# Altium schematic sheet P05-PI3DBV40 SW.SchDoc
size 386 x 246 mm
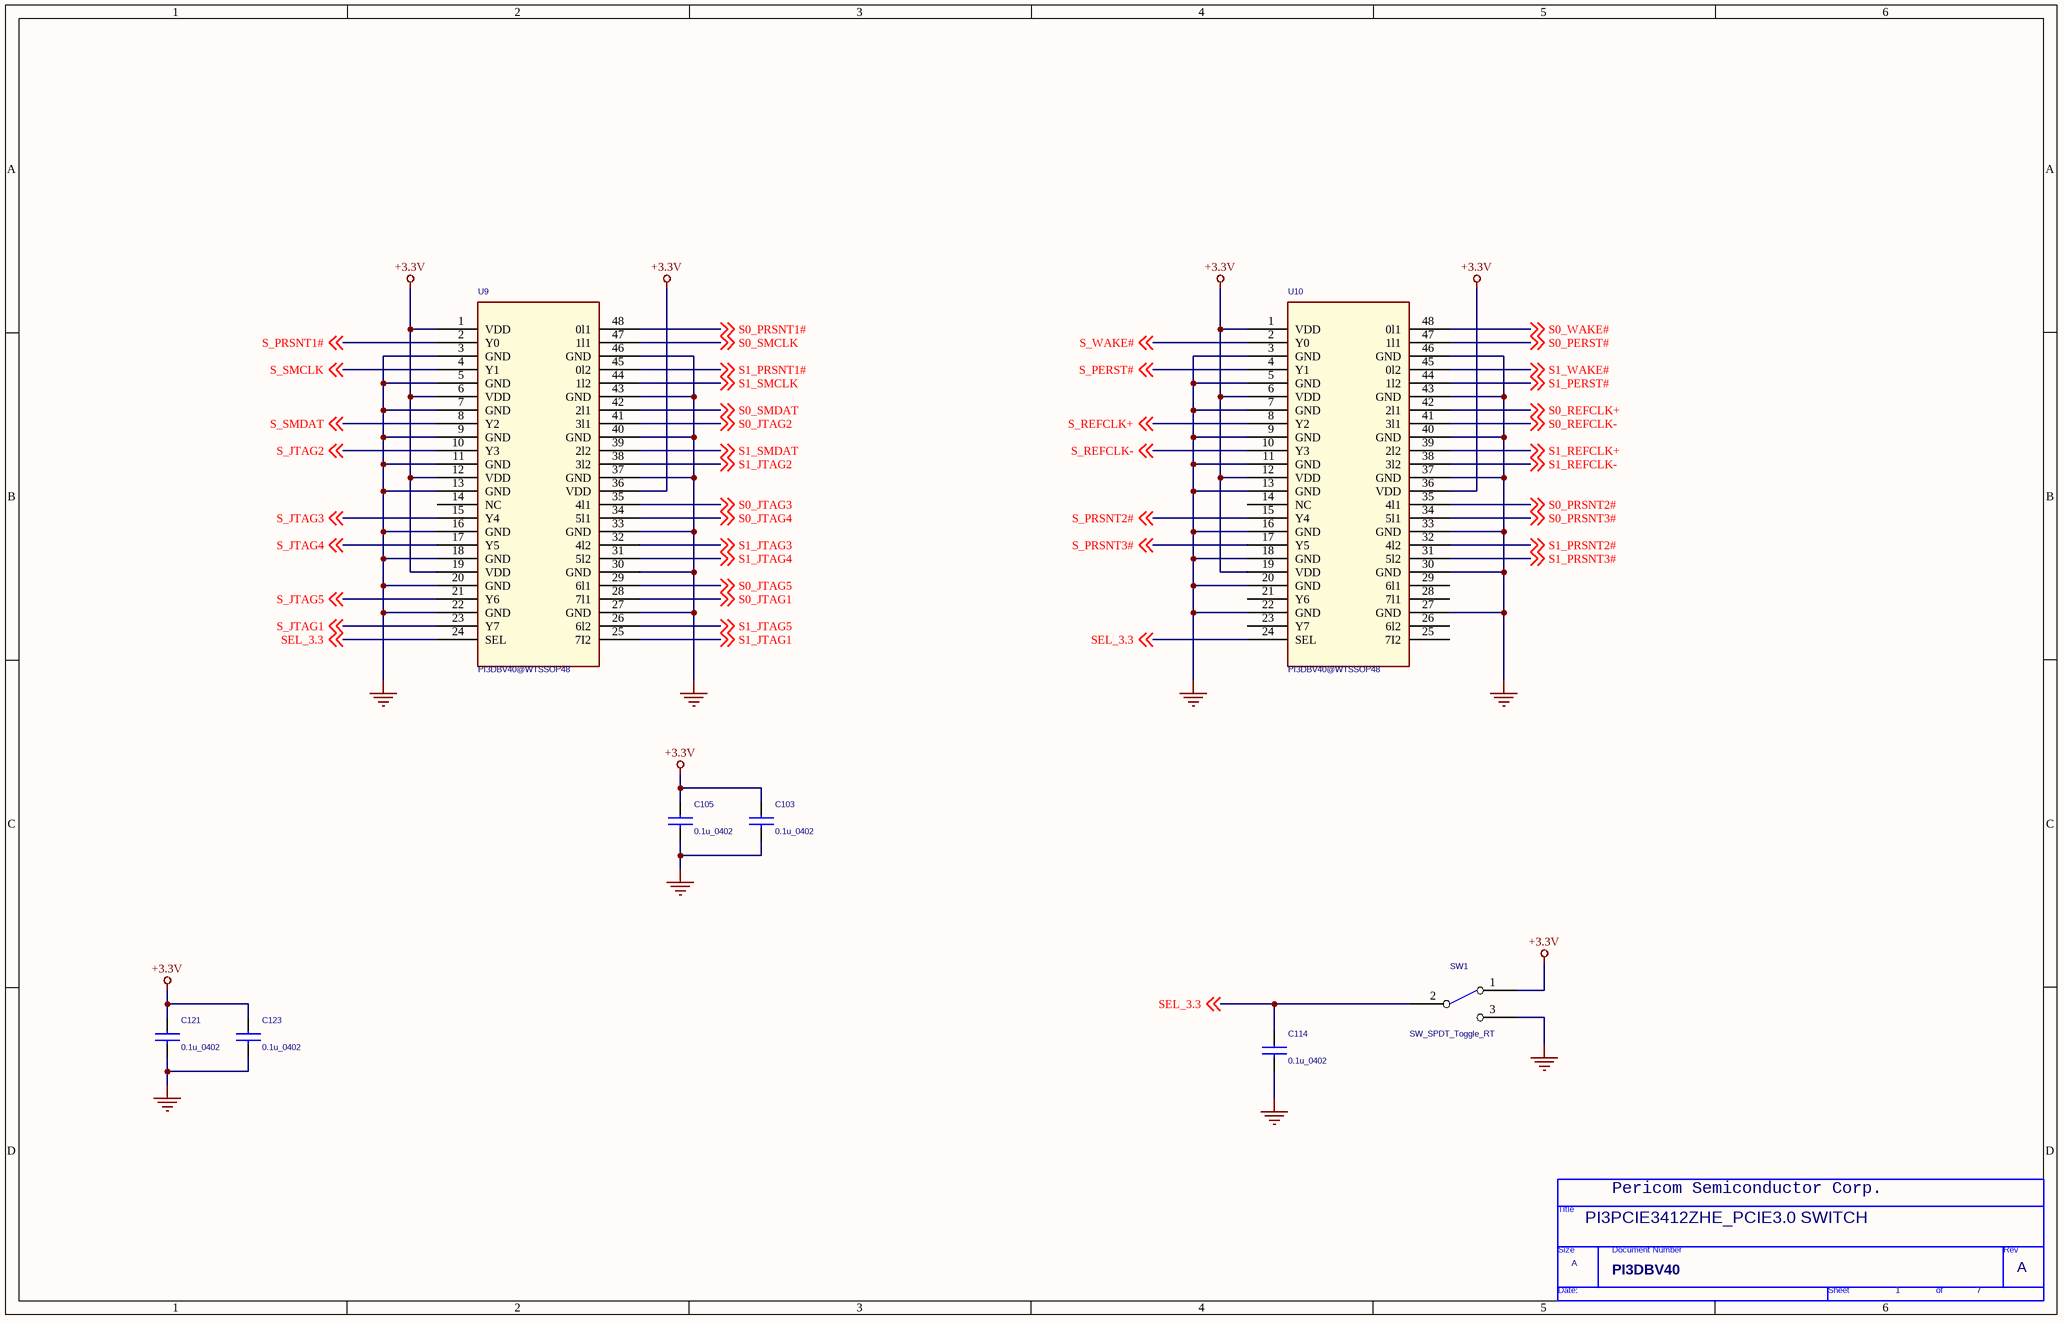
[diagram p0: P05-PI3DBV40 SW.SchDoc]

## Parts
*  Doc: PI3DBV40  RevCode: A  Title: PI3PCIE3412ZHE_PCIE3.0 SWITCH  Page Number: 1  Page Count: 7  (hidden comment: TitleBlock0)  (graphical)
C103  0.1u_0402  [CC_0402]
C105  0.1u_0402  [CC_0402]
C114  0.1u_0402  [CC_0402]
C121  0.1u_0402  [CC_0402]
C123  0.1u_0402  [CC_0402]
SW1  SW_SPDT_Toggle_RT  [SWSPDT]
U9  PI3DBV40@WTSSOP48  [WTSSOP48]
U10  PI3DBV40@WTSSOP48  [WTSSOP48]

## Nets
+3.3V: C103.1 C105.1 C121.1 C123.1 SW1.1(NC) U9.1(VDD) U9.6(VDD) U9.12(VDD) U9.19(VDD) U9.36(VDD) U10.1(VDD) U10.6(VDD) U10.12(VDD) U10.19(VDD) U10.36(VDD)
GND: C103.2 C105.2 C114.2 C121.2 C123.2 SW1.3(NO) U9.3(GND) U9.5(GND) U9.7(GND) U9.9(GND) U9.11(GND) U9.13(GND) U9.16(GND) U9.18(GND) U9.20(GND) U9.22(GND) U9.27(GND) U9.30(GND) U9.33(GND) U9.37(GND) U9.40(GND) U9.43(GND) U9.46(GND) U10.3(GND) U10.5(GND) U10.7(GND) U10.9(GND) U10.11(GND) U10.13(GND) U10.16(GND) U10.18(GND) U10.20(GND) U10.22(GND) U10.27(GND) U10.30(GND) U10.33(GND) U10.37(GND) U10.40(GND) U10.43(GND) U10.46(GND)
S0_JTAG1: U9.28(7l1) ; off-sheet S0_JTAG1
S0_JTAG2: U9.41(3l1) ; off-sheet S0_JTAG2
S0_JTAG3: U9.35(4l1) ; off-sheet S0_JTAG3
S0_JTAG4: U9.34(5l1) ; off-sheet S0_JTAG4
S0_JTAG5: U9.29(6l1) ; off-sheet S0_JTAG5
S0_PERST#: U10.47(1l1) ; off-sheet S0_PERST#
S0_PRSNT1#: U9.48(0l1) ; off-sheet S0_PRSNT1#
S0_PRSNT2#: U10.35(4l1) ; off-sheet S0_PRSNT2#
S0_PRSNT3#: U10.34(5l1) ; off-sheet S0_PRSNT3#
S0_REFCLK+: U10.42(2l1) ; off-sheet S0_REFCLK+
S0_REFCLK-: U10.41(3l1) ; off-sheet S0_REFCLK-
S0_SMCLK: U9.47(1l1) ; off-sheet S0_SMCLK
S0_SMDAT: U9.42(2l1) ; off-sheet S0_SMDAT
S0_WAKE#: U10.48(0l1) ; off-sheet S0_WAKE#
S1_JTAG1: U9.25(7I2) ; off-sheet S1_JTAG1
S1_JTAG2: U9.38(3l2) ; off-sheet S1_JTAG2
S1_JTAG3: U9.32(4l2) ; off-sheet S1_JTAG3
S1_JTAG4: U9.31(5l2) ; off-sheet S1_JTAG4
S1_JTAG5: U9.26(6l2) ; off-sheet S1_JTAG5
S1_PERST#: U10.44(1l2) ; off-sheet S1_PERST#
S1_PRSNT1#: U9.45(0l2) ; off-sheet S1_PRSNT1#
S1_PRSNT2#: U10.32(4l2) ; off-sheet S1_PRSNT2#
S1_PRSNT3#: U10.31(5l2) ; off-sheet S1_PRSNT3#
S1_REFCLK+: U10.39(2l2) ; off-sheet S1_REFCLK+
S1_REFCLK-: U10.38(3l2) ; off-sheet S1_REFCLK-
S1_SMCLK: U9.44(1l2) ; off-sheet S1_SMCLK
S1_SMDAT: U9.39(2l2) ; off-sheet S1_SMDAT
S1_WAKE#: U10.45(0l2) ; off-sheet S1_WAKE#
S_JTAG1: U9.23(Y7) ; off-sheet S_JTAG1
S_JTAG2: U9.10(Y3) ; off-sheet S_JTAG2
S_JTAG3: U9.15(Y4) ; off-sheet S_JTAG3
S_JTAG4: U9.17(Y5) ; off-sheet S_JTAG4
S_JTAG5: U9.21(Y6) ; off-sheet S_JTAG5
S_PERST#: U10.4(Y1) ; off-sheet S_PERST#
S_PRSNT1#: U9.2(Y0) ; off-sheet S_PRSNT1#
S_PRSNT2#: U10.15(Y4) ; off-sheet S_PRSNT2#
S_PRSNT3#: U10.17(Y5) ; off-sheet S_PRSNT3#
S_REFCLK+: U10.8(Y2) ; off-sheet S_REFCLK+
S_REFCLK-: U10.10(Y3) ; off-sheet S_REFCLK-
S_SMCLK: U9.4(Y1) ; off-sheet S_SMCLK
S_SMDAT: U9.8(Y2) ; off-sheet S_SMDAT
S_WAKE#: U10.2(Y0) ; off-sheet S_WAKE#
SEL_3.3: C114.1 SW1.2(COMMON) U9.24(SEL) U10.24(SEL) ; off-sheet SEL_3.3

Not connected (* = marked no-connect by the designer): U9 14(NC); U10 14(NC) 21(Y6) 23(Y7) 25(7I2) 26(6l2) 28(7l1) 29(6l1)

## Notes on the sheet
- Pericom Semiconductor Corp.

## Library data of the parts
C103 C105 C114 C121 C123 = C_0.1u_0402
U9 U10 = PI3DBV40@WTSSOP48_0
